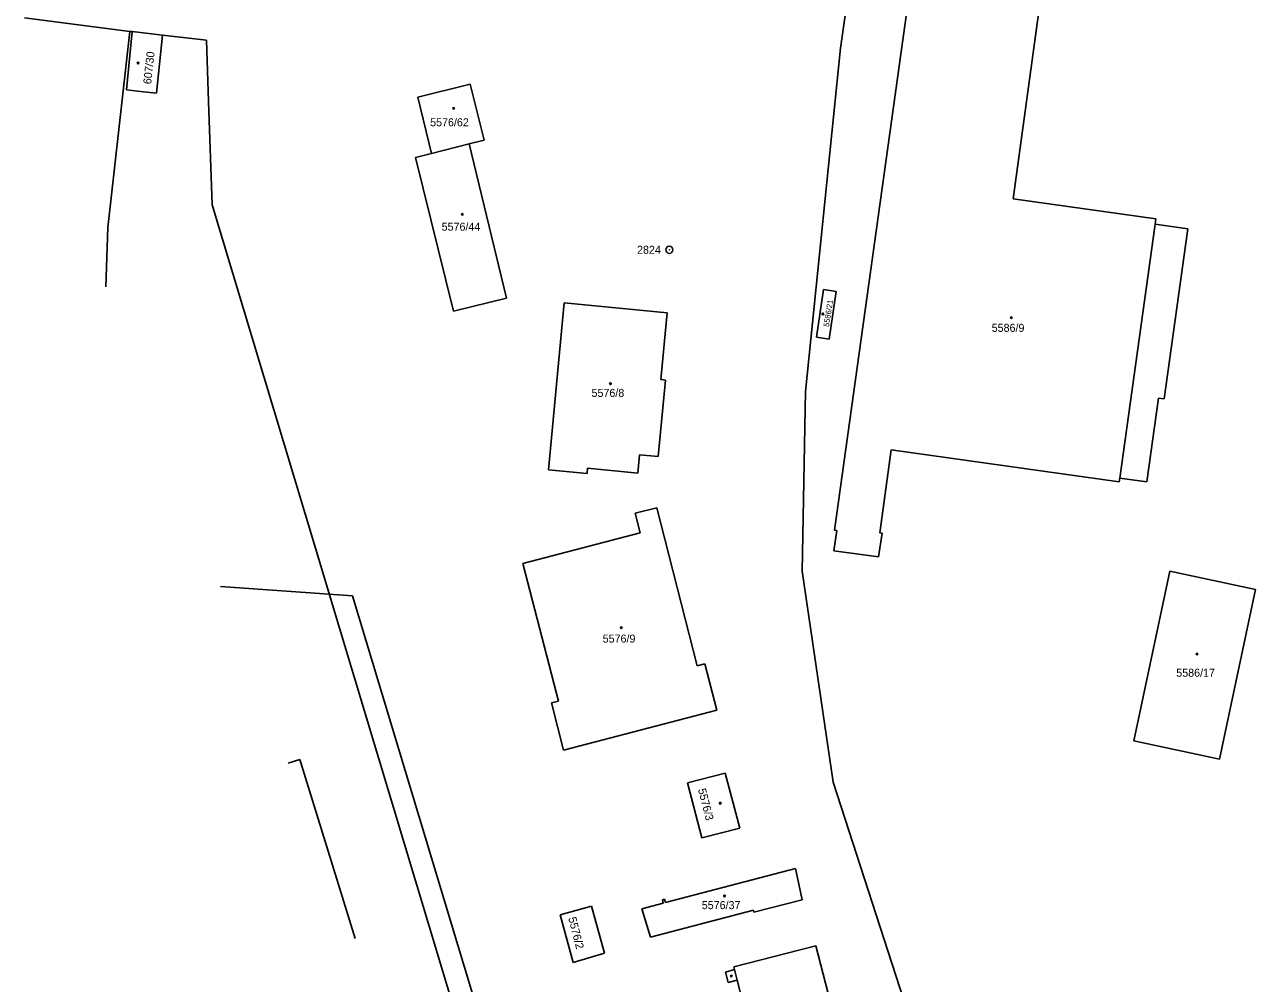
# Model space of a CAD drawing. Extents: x -825057 to -819383, y -1071633 to -1067888.
# Drawn here: x -820904.8 to -820643.4, y -1068876.3 to -1068672.6 of the extents above; entities that cross this region are included whole.
import ezdxf

# ---------------------------------------------------------------- set-up
doc = ezdxf.new("R2010")
doc.units = 0
for name, color, linetype in [('Vrstva 1', 7, 'Continuous'), ('Vrstva 12', 7, 'Continuous'), ('Vrstva 17', 7, 'Continuous'), ('Vrstva 18', 7, 'Continuous'), ('Vrstva 19', 7, 'Continuous'), ('Vrstva 24', 7, 'Continuous'), ('Vrstva 25', 7, 'Continuous'), ('Vrstva 4', 7, 'Continuous')]:
    doc.layers.add(name, color=color, linetype=linetype)

msp = doc.modelspace()

# ---------------------------------------------------------------- linework, layer by layer
at = {"layer": 'Vrstva 1'}
for p, q in [((-820731.5, -1068677.6), (-820726.56, -1068641.95)), ((-820715.76, -1068657.77), (-820732.79, -1068779.98)), ((-820694.85, -1068709.64), (-820688.27, -1068661.5)), ((-820904.79, -1068671.17), (-820882.46, -1068674.04)), ((-820882.46, -1068674.04), (-820887.15, -1068715.69)), ((-820883.17, -1068686.44), (-820881.95, -1068674.1)), ((-820882.46, -1068674.04), (-820881.95, -1068674.1)), ((-820881.95, -1068674.1), (-820875.49, -1068674.84)), ((-820875.49, -1068674.84), (-820876.81, -1068687.17)), ((-820875.49, -1068674.84), (-820866.19, -1068675.9)), ((-820866.19, -1068675.9), (-820865.74, -1068688.91)), ((-820739, -1068750.5), (-820731.5, -1068677.6)), ((-820810.17, -1068685.27), (-820821.31, -1068688.03)), ((-820807.22, -1068697.18), (-820810.17, -1068685.27)), ((-820879.54, -1068686.85), (-820883.17, -1068686.44)), ((-820876.81, -1068687.17), (-820879.54, -1068686.85)), ((-820865.74, -1068688.91), (-820864.98, -1068710.9)), ((-820821.31, -1068688.03), (-820818.37, -1068699.99)), ((-820818.37, -1068699.99), (-820810.42, -1068697.94)), ((-820810.42, -1068697.94), (-820807.22, -1068697.18)), ((-820802.44, -1068730.69), (-820810.42, -1068697.94)), ((-820818.37, -1068699.99), (-820821.81, -1068700.85)), ((-820821.81, -1068700.85), (-820813.74, -1068733.5)), ((-820840.84, -1068791.11), (-820864.98, -1068710.9)), ((-820664.59, -1068713.89), (-820694.85, -1068709.64)), ((-820664.7, -1068715.01), (-820664.59, -1068713.89)), ((-820887.51, -1068728.28), (-820887.15, -1068715.69)), ((-820657.79, -1068716.01), (-820664.7, -1068715.01)), ((-820662.79, -1068752.1), (-820657.79, -1068716.01)), ((-820735.14, -1068728.89), (-820736.6, -1068739.02)), ((-820732.47, -1068729.29), (-820735.14, -1068728.89)), ((-820733.96, -1068739.41), (-820732.47, -1068729.29)), ((-820813.74, -1068733.5), (-820802.44, -1068730.69)), ((-820793.57, -1068767.15), (-820790.18, -1068731.73)), ((-820790.18, -1068731.73), (-820768.33, -1068733.82)), ((-820768.33, -1068733.82), (-820769.71, -1068748.02)), ((-820736.6, -1068739.02), (-820733.96, -1068739.41)), ((-820769.71, -1068748.02), (-820768.71, -1068748.11)), ((-820768.71, -1068748.11), (-820770.26, -1068764.35)), ((-820739.7, -1068788.7), (-820739, -1068750.5)), ((-820666.49, -1068769.74), (-820663.98, -1068751.94)), ((-820663.98, -1068751.94), (-820662.79, -1068752.1)), ((-820723.15, -1068780.56), (-820720.74, -1068762.93)), ((-820720.74, -1068762.93), (-820672.39, -1068769.71)), ((-820774.2, -1068764.02), (-820774.57, -1068767.87)), ((-820770.26, -1068764.35), (-820774.2, -1068764.02)), ((-820785.36, -1068767.94), (-820793.57, -1068767.15)), ((-820785.25, -1068766.84), (-820785.36, -1068767.94)), ((-820774.57, -1068767.87), (-820785.25, -1068766.84)), ((-820672.39, -1068769.71), (-820672.24, -1068768.94)), ((-820672.24, -1068768.94), (-820666.49, -1068769.74)), ((-820775.12, -1068776.37), (-820770.57, -1068775.21)), ((-820774.06, -1068780.54), (-820775.12, -1068776.37)), ((-820770.57, -1068775.21), (-820761.98, -1068808.8)), ((-820798.96, -1068787.09), (-820774.06, -1068780.54)), ((-820732.32, -1068780.05), (-820732.92, -1068784.36)), ((-820732.79, -1068779.98), (-820732.32, -1068780.05)), ((-820723.48, -1068785.68), (-820722.68, -1068780.66)), ((-820722.68, -1068780.66), (-820723.15, -1068780.56)), ((-820732.92, -1068784.36), (-820723.48, -1068785.68)), ((-820791.43, -1068816.31), (-820798.96, -1068787.09)), ((-820733.1, -1068833.5), (-820739.7, -1068788.7)), ((-820661.59, -1068788.73), (-820669.23, -1068824.73)), ((-820643.43, -1068792.61), (-820661.59, -1068788.73)), ((-820840.25, -1068793.05), (-820840.84, -1068791.11)), ((-820809.49, -1068895.25), (-820840.25, -1068793.05)), ((-820651.03, -1068828.6), (-820643.43, -1068792.61)), ((-820761.98, -1068808.8), (-820760.33, -1068808.38)), ((-820760.33, -1068808.38), (-820757.79, -1068818.23)), ((-820792.88, -1068816.68), (-820791.43, -1068816.31)), ((-820790.33, -1068826.74), (-820792.88, -1068816.68)), ((-820757.79, -1068818.23), (-820790.33, -1068826.74)), ((-820669.23, -1068824.73), (-820651.03, -1068828.6)), ((-820848.84, -1068829.5), (-820846.32, -1068828.72)), ((-820834.62, -1068866.74), (-820846.32, -1068828.72)), ((-820764.01, -1068833.65), (-820755.99, -1068831.57)), ((-820755.99, -1068831.57), (-820752.91, -1068843.29)), ((-820760.98, -1068845.31), (-820764.01, -1068833.65)), ((-820717.06, -1068883.02), (-820733.1, -1068833.5)), ((-820752.91, -1068843.29), (-820760.98, -1068845.31)), ((-820741.12, -1068851.88), (-820768.66, -1068859.07)), ((-820739.68, -1068858.53), (-820741.12, -1068851.88)), ((-820791.05, -1068861.7), (-820784.44, -1068859.82)), ((-820784.44, -1068859.82), (-820781.65, -1068869.87)), ((-820769.2, -1068859.19), (-820773.73, -1068860.39)), ((-820773.73, -1068860.39), (-820771.9, -1068866.43)), ((-820768.89, -1068858.38), (-820769.33, -1068858.5)), ((-820769.33, -1068858.5), (-820769.2, -1068859.19)), ((-820768.66, -1068859.07), (-820768.89, -1068858.38)), ((-820749.91, -1068861.16), (-820739.68, -1068858.53)), ((-820788.29, -1068871.81), (-820791.05, -1068861.7)), ((-820771.9, -1068866.43), (-820750.03, -1068860.72)), ((-820750.03, -1068860.72), (-820749.91, -1068861.16)), ((-820740.12, -1068869.13), (-820736.79, -1068868.28)), ((-820736.79, -1068868.28), (-820731.64, -1068888.19)), ((-820781.65, -1068869.87), (-820788.29, -1068871.81)), ((-820754.19, -1068872.72), (-820740.12, -1068869.13)), ((-820755.96, -1068873.84), (-820754.03, -1068873.34)), ((-820754.03, -1068873.34), (-820754.19, -1068872.72)), ((-820755.39, -1068876.06), (-820755.96, -1068873.84)), ((-820753.46, -1068875.56), (-820755.39, -1068876.06)), ((-820749, -1068892.87), (-820753.46, -1068875.56))]:
    msp.add_line(p, q, dxfattribs=at)
at = {"layer": 'Vrstva 12'}
for p, q in [((-820835.14, -1068793.96), (-820863.18, -1068791.96)), ((-820835.14, -1068793.96), (-820863.18, -1068791.96)), ((-820805.66, -1068891.68), (-820835.14, -1068793.96)), ((-820805.66, -1068891.68), (-820835.14, -1068793.96))]:
    msp.add_line(p, q, dxfattribs=at)
at = {"layer": 'Vrstva 24'}
for radius in [0.75, 0.75, 0.0327, 0.0327]:
    msp.add_circle((-820767.88, -1068720.44), radius, dxfattribs=at)
at = {"layer": 'Vrstva 25'}
for centre in [(-820880.68, -1068680.76), (-820880.68, -1068680.76), (-820813.68, -1068690.39), (-820813.68, -1068690.39), (-820811.85, -1068712.9), (-820811.85, -1068712.9), (-820735.28, -1068734.06), (-820735.28, -1068734.06), (-820695.25, -1068734.85), (-820695.25, -1068734.85), (-820780.39, -1068748.88), (-820780.39, -1068748.88), (-820778.08, -1068800.71), (-820778.08, -1068800.71), (-820655.84, -1068806.29), (-820655.84, -1068806.29), (-820757.08, -1068837.98), (-820757.08, -1068837.98), (-820756.16, -1068857.7), (-820756.16, -1068857.7), (-820754.71, -1068874.7), (-820754.71, -1068874.7)]:
    msp.add_circle(centre, 0.175, dxfattribs=at)
at = {"layer": 'Vrstva 4'}
for p, q in [((-820672.24, -1068768.94), (-820664.7, -1068715.01)), ((-820753.46, -1068875.56), (-820754.03, -1068873.34))]:
    msp.add_line(p, q, dxfattribs=at)

# ---------------------------------------------------------------- texts
at = {"layer": 'Vrstva 17'}
msp.add_text('2824', height=1.7, dxfattribs=at).set_placement((-820774.739, -1068721.28))
msp.add_text('2824', height=1.7, dxfattribs=at).set_placement((-820774.739, -1068721.28))
at = {"layer": 'Vrstva 18'}
msp.add_text('5576/2', height=1.7, rotation=284.4, dxfattribs=at).set_placement((-820789.353, -1068862.378))
msp.add_text('5576/2', height=1.7, rotation=284.4, dxfattribs=at).set_placement((-820789.353, -1068862.378))
at = {"layer": 'Vrstva 19'}
for s, height, rotation, p in [('607/30', 1.7, 83.7, (-820877.929, -1068685.333)), ('607/30', 1.7, 83.7, (-820877.929, -1068685.333)), ('5586/21', 1.2, 81, (-820733.99, -1068736.88)), ('5586/21', 1.2, 81, (-820733.99, -1068736.88)), ('5576/3', 1.7, 284.4, (-820761.806, -1068835.066)), ('5576/3', 1.7, 284.4, (-820761.806, -1068835.066))]:
    msp.add_text(s, height=height, rotation=rotation, dxfattribs=at).set_placement(p)
for s, p in [('5576/62', (-820818.678, -1068694.2)), ('5576/62', (-820818.678, -1068694.2)), ('5576/44', (-820816.232, -1068716.37)), ('5576/44', (-820816.232, -1068716.37)), ('5586/9', (-820699.424, -1068737.86)), ('5586/9', (-820699.424, -1068737.86)), ('5576/8', (-820784.402, -1068751.68)), ('5576/8', (-820784.402, -1068751.68)), ('5576/9', (-820782.034, -1068803.87)), ('5576/9', (-820782.034, -1068803.87)), ('5586/17', (-820660.23, -1068811.12)), ('5586/17', (-820660.23, -1068811.12)), ('5576/37', (-820760.99, -1068860.48)), ('5576/37', (-820760.99, -1068860.48))]:
    msp.add_text(s, height=1.7, dxfattribs=at).set_placement(p)

doc.saveas('drawing.dxf')
